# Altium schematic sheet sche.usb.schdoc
size 297 x 209 mm; Symbol: Sheet-Symbol_A4; Border: 1; Title Block Position: 3; Width: 1170; Height: 825; Region Start: 1; X Region Count: 6; Y Region Count: 4; Blade Width: 10; Title Block: 1; @Board Name: NandFlash; @Create Time: 22:09:13; @Update Time: 23:23:41; Company: 嘉立创EDA; Version: V1.0; Page Size: A4; @Project Name: 木马派(Mumap) Linux卡片电脑-RV1106G; @Page Count: 10; @Update Date: 2025-02-18; @Create Date: 2024-11-25; @Schematic Name: Schematic1; @Page No: 4; @Page Name: USB/Wifi; Device: Sheet-Symbol_A4
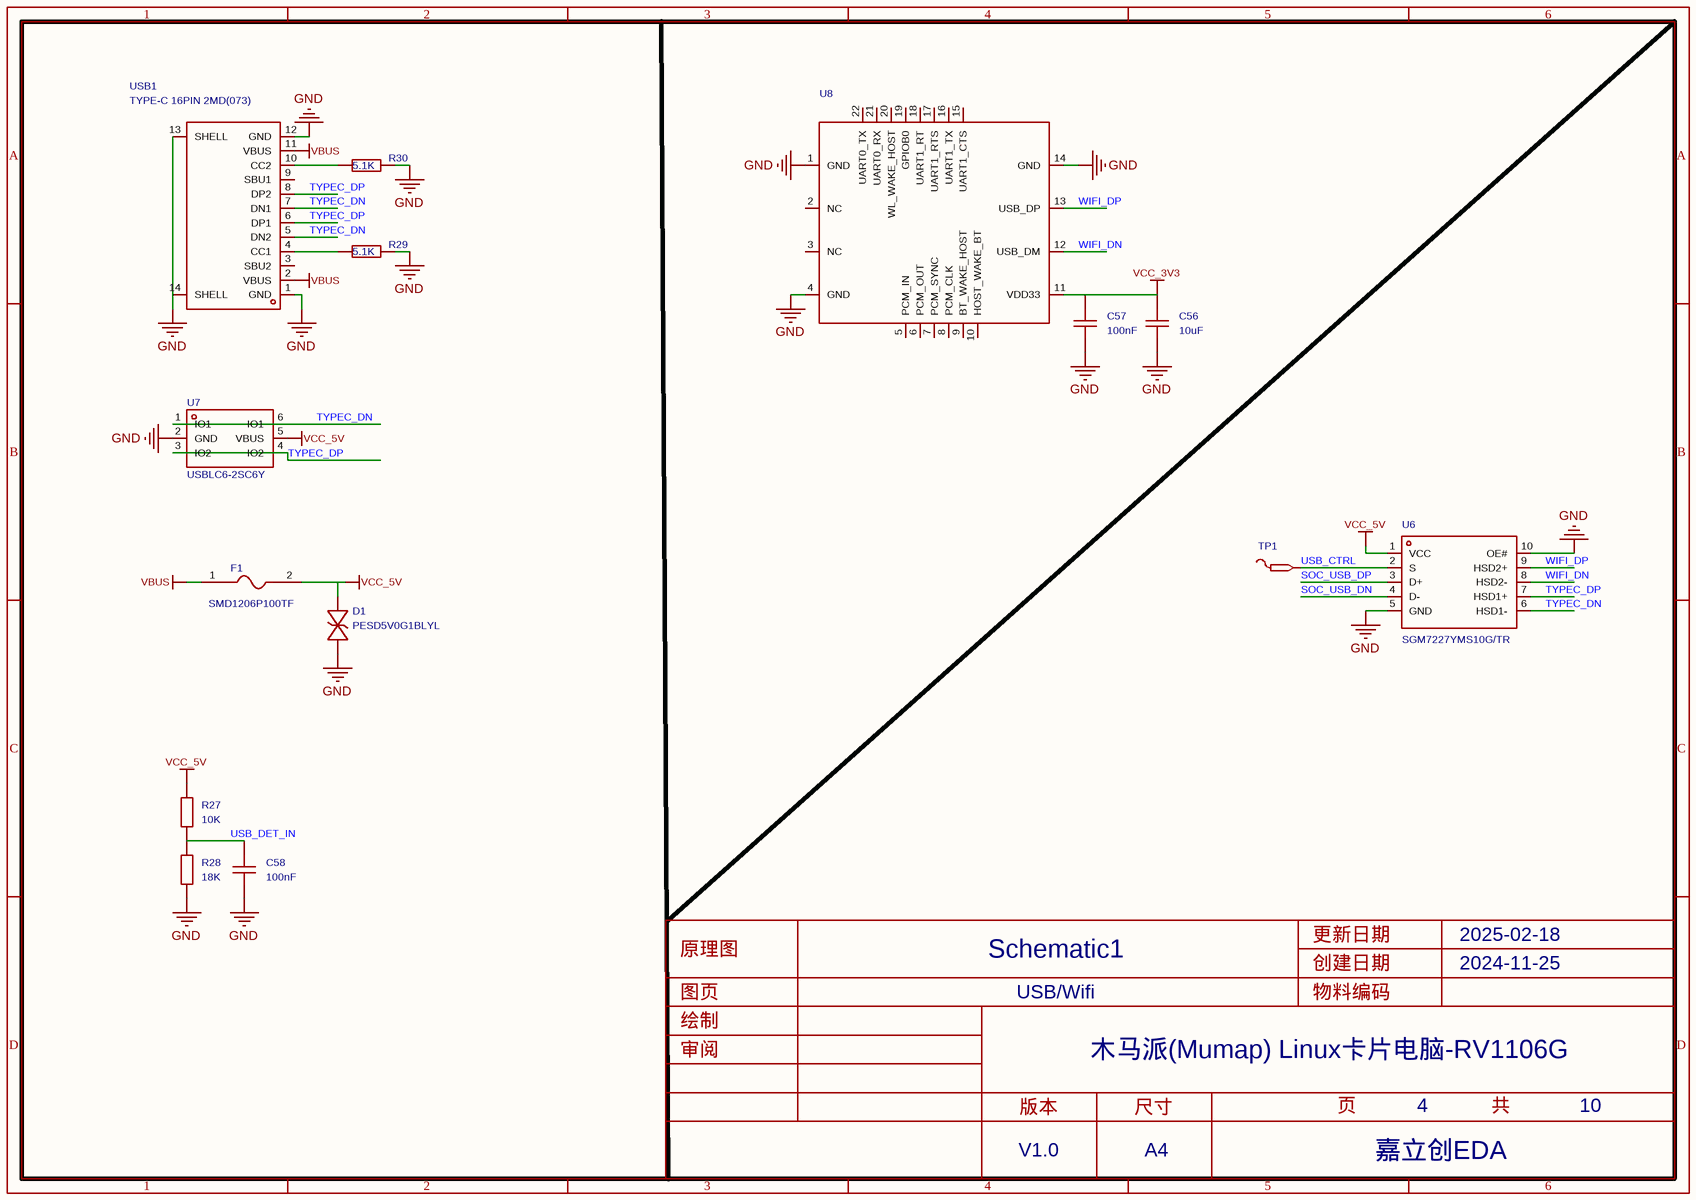
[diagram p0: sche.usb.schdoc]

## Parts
C56  10uF  [C0603]
C57  100nF  [C0402]
C58  100nF  [C0402]
D1  PESD5V0G1BLYL  [DFN1006-2L-BI-1]
F1  SMD1206P100TF  [F1206]
R27  10K  [R0402]
R28  18K  [R0402]
R29  5.1K  [R0402]
R30  5.1K  [R0402]
TP1  (no value)  [Test-Point-0.5mm]
U6  SGM7227YMS10G/TR  [MSOP-10_L3.0-W3.0-P0.50-LS5.0-BL]
U7  USBLC6-2SC6Y  [SOT-23-6_L2.9-W1.7-P0.95-LS2.8-BL]
U8  (no value)  [AIC8800DC]
USB1  TYPE-C 16PIN 2MD(073)  [USB-C-SMD_TYPE-C-6PIN-2MD-073]

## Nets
GND: C56.1 C57.1 C58.1 D1.1 R28.1 R29.2 R30.2 U6.5(GND) U6.10(OE#) U7.2(GND) U8.1(GND) U8.4(GND) U8.14(GND) USB1.1(GND) USB1.12(GND) USB1.13(SHELL) USB1.14(SHELL)
VBUS: F1.1 USB1.2(VBUS) USB1.11(VBUS)
VCC_3V3: C56.2 C57.2 U8.11(VDD33)
VCC_5V: D1.2 F1.2 R27.2 U6.1(VCC) U7.5(VBUS)
SOC_USB_DN: U6.4(D-)
SOC_USB_DP: U6.3(D+)
TYPEC_DN: U6.6(HSD1-) U7.1(IO1) U7.6(IO1) USB1.5(DN2) USB1.7(DN1)
TYPEC_DP: U6.7(HSD1+) U7.3(IO2) U7.4(IO2) USB1.6(DP1) USB1.8(DP2)
USB_CTRL: TP1.1 U6.2(S)
USB_DET_IN: C58.2 R27.1 R28.2
WIFI_DN: U6.8(HSD2-) U8.12(USB_DM)
WIFI_DP: U6.9(HSD2+) U8.13(USB_DP)
NetR29_1: R29.1 USB1.4(CC1)
NetR30_1: R30.1 USB1.10(CC2)

Not connected (* = marked no-connect by the designer): U8 2(NC) 3(NC) 5(PCM_IN) 6(PCM_OUT) 7(PCM_SYNC) 8(PCM_CLK) 9(BT_WAKE_HOST) 10(HOST_WAKE_BT) 15(UART1_CTS) 16(UART1_TX) 17(UART1_RTS) 18(UART1_RT) 19(GPIOB0) 20(WL_WAKE_HOST) 21(UART0_RX) 22(UART0_TX); USB1 3(SBU2) 9(SBU1)

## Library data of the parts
C56 = CAP_0603: Symbol: CapAcitance; ConvertToPcb: yes; ModelId: ac125912035d415993ca9572d50418b1; ModelName: C0603_L1.6-W0.8-H0.8; ModelTransform: 62.992,31.496,0,0,0,0,0,0,0
C57 C58 = CAP_0402: Symbol: CapAcitance; ConvertToPcb: yes; ModelId: 36a51122f27c49738f86b3bfa98863e0; ModelName: C0402_L1.0-W0.5-H0.5; ModelTransform: 39.37,19.685,0,0,0,0,0,0,0
D1 = PESD5V0G1BLYL: Manufacturer: Nexperia(安世); AddInBom: yes; ModelId: 4f73e746f3be4d299816d29f03249d6e; ModelTransform: 40.1574,24.4094,0,0,0,0,0,0,0
F1 = SMD1206P100TF: 最大电压:6V;最大电流:100A;保持电流:1A;跳闸电流:1.8A;; Manufacturer: RUILON(瑞隆源); AddInBom: yes; ModelId: f1628daad26847a79b887277a2bc8541; ModelName: F1206_L3.2-W1.7-H0.6; ModelTransform: 125.984,66.929,0,0,0,0,0,0,0; Operating Voltage (Max): 6V; Current Rating (Max): 100A; Hold Current: 1A; Trip Current: 1.8A
R27-R30 = Res_0402: Symbol: 电阻; ConvertToPcb: yes; ModelId: 671aefced39d4c318694bba8bd8efd39; ModelName: R0402_L1.0-W0.5-H0.5; ModelTransform: 39.37,19.685,0,0,0,0,0,0.0005,0
TP1 = Test-Point: Test Point 测试点; AddInBom: yes
U6 = SGM7227YMS10G/TR: 开关电路:-;; Manufacturer: SGMICRO(圣邦微); AddInBom: yes; ModelId: b42a31f9e1fa4643bc7ea573b9bba7ed; ModelName: MSOP-10_L3.0-W3.0-H1.1-LS5.0-P0.50; ModelTransform: 118.11,196.85,0,0,0,0,0,0,0
U7 = USBLC6-2SC6Y_C2969755: 最大钳位电压:17V;击穿电压:6V;; Manufacturer: ST(意法半导体); AddInBom: yes; ModelId: f198fe6923cc4b1fabccb73198a22cca; ModelTransform: 114.173,110.236,0,0,0,0,0,0,0; Maximum Clamping Voltage: 17V; Breakdown Voltage: 6V; Number of Lines: 双路
U8 = AIC8800DC: AddInBom: yes; ModelId: 33d97bcc7b6c468da6c6168ea59e00b10819f05c4eef4c71ace90d822a990e87; ModelName: WIFIM-SMD_20P-L12.9-W12.2_RTL8731BU; ModelTransform: 480.31,507.87,79.53,0,0,0,0,0,0
USB1 = TYPE-C 16PIN 2MD(073): 连接器类型:Type-C;标准:USB 3.1;公母:母;安装方式:卧贴;触点数量:16P;端口数量:1;额定电流 - 电源:5A;工作温度范围:-25℃~+85℃;; Manufacturer: SHOU HAN(首韩); AddInBom: yes; ModelId: 3a41b9ec9b654a0fad4d118405ec6290; ModelTransform: 351.9678,298.4246,0,0,0,0,0,-47.244,-35.433; Gender: 母; Number of Contacts: 16P; Number of Ports: 1; Current Rating - Power (Max): 5A; Rated Voltage (Max): 5V; Connect-Disconnect Life: 5千次; Core Colour: 黑色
